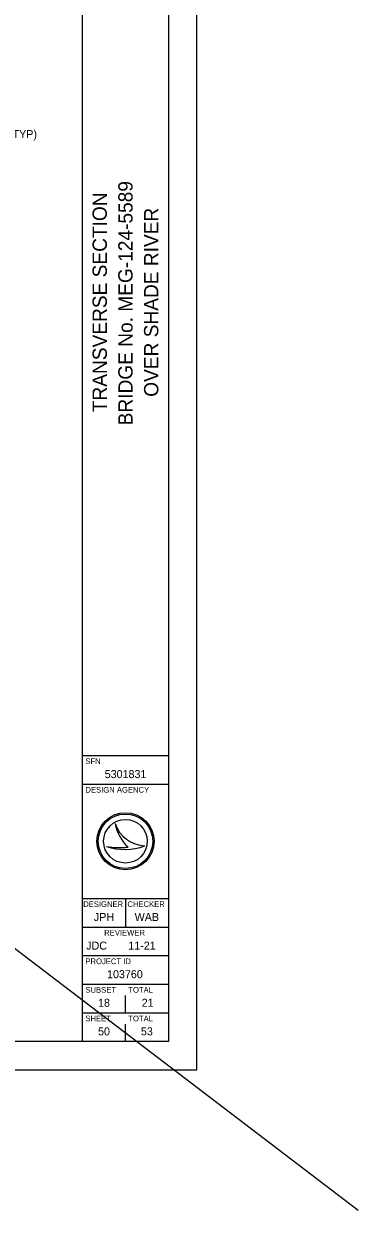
# Model space of a CAD drawing. Extents: x -86 to 68, y -5 to 62.
# Drawn here: x -33.58 to -24.81, y -5.09 to 26.04 of the extents above; entities that cross this region are included whole.
import ezdxf

# ---------------------------------------------------------------- set-up
doc = ezdxf.new("R2010")
doc.units = 0
for name, color, linetype in [('SH_Border', 7, 'Continuous'), ('SH_Cut_Line', 7, 'Continuous'), ('SH_Data', 7, 'Continuous'), ('TX_P_1', 7, 'Continuous')]:
    doc.layers.add(name, color=color, linetype=linetype)

msp = doc.modelspace()

# ---------------------------------------------------------------- linework, layer by layer
at = {"layer": 'SH_Border'}
for p, q in [((-32.038, -0.659), (-32.038, 30.841)), ((-32.038, 6.841), (-29.788, 6.841)), ((-32.038, 6.091), (-29.788, 6.091)), ((-32.038, 3.091), (-29.788, 3.091)), ((-30.913, 3.091), (-30.913, 2.341)), ((-32.038, 2.341), (-29.788, 2.341)), ((-32.038, 1.591), (-29.788, 1.591)), ((-32.038, 0.841), (-29.788, 0.841)), ((-32.038, 0.091), (-29.788, 0.091))]:
    msp.add_line(p, q, dxfattribs=at)
msp.add_lwpolyline([(-77.788, 30.841), (-29.788, 30.841), (-29.788, -0.659), (-77.788, -0.659)], close=True, dxfattribs=at)
at = {"layer": 'SH_Cut_Line'}
msp.add_lwpolyline([(-80.038, -1.409), (-29.038, -1.409), (-29.038, 31.591), (-80.038, 31.591)], close=True, dxfattribs=at)
at = {"layer": 'SH_Data'}
for p, q in [((-31.187, 5.055), (-31.187, 5.055)), ((-31.413, 4.455), (-31.413, 4.455)), ((-30.913, 4.591), (-30.913, 4.591)), ((-30.407, 4.468), (-30.407, 4.468)), ((-30.913, 0.091), (-30.913, 0.541)), ((-30.913, -0.659), (-30.913, -0.209)), ((-31.476, -0.397), (-31.476, -0.397))]:
    msp.add_line(p, q, dxfattribs=at)
for radius in [0.75, 0.715, 0.715, 0.573]:
    msp.add_circle((-30.913, 4.591), radius, dxfattribs=at)
for centre, radius, start, end in [((-30.364, 5.337), 0.87, 198.9257, 198.9319), ((-30.018, 5.296), 1.193, 191.6379, 191.6421), ((-30.364, 5.337), 0.87, 198.9319, 267.1657), ((-30.018, 5.296), 1.193, 191.6421, 226.0947), ((-30.929, 5.896), 1.52, 251.4576, 290.0832), ((-31.066, 6.322), 1.899, 259.4964, 259.4995), ((-30.929, 5.896), 1.52, 251.4527, 251.4576), ((-31.066, 6.322), 1.899, 259.4995, 276.6672)]:
    msp.add_arc(centre, radius, start, end, dxfattribs=at)
at = {"layer": 'TX_P_1'}
msp.add_line((-86.356, 41.867), (-24.807, -5.092), dxfattribs=at)

# ---------------------------------------------------------------- texts
at = {"layer": 'SH_Data'}
for s, p in [('BRIDGE No. MEG-124-5589', (-30.726, 15.504)), ('TRANSVERSE SECTION', (-31.401, 15.848)), ('OVER SHADE RIVER', (-30.051, 16.253))]:
    msp.add_text(s, height=0.375, rotation=90, dxfattribs=at).set_placement(p)
for s, height, p in [('SFN', 0.15, (-31.963, 6.616)), ('5301831', 0.21, (-31.457, 6.248)), ('DESIGN AGENCY', 0.15, (-31.963, 5.866)), ('DESIGNER', 0.15, (-32.022, 2.866)), ('CHECKER', 0.15, (-30.862, 2.866)), ('JPH', 0.21, (-31.741, 2.498)), ('WAB', 0.21, (-30.672, 2.498)), ('REVIEWER', 0.15, (-31.471, 2.116)), ('JDC', 0.21, (-31.943, 1.748)), ('11-21', 0.21, (-30.838, 1.748)), ('PROJECT ID', 0.15, (-31.963, 1.366)), ('103760', 0.21, (-31.396, 0.998)), ('SUBSET', 0.15, (-31.963, 0.616)), ('TOTAL', 0.15, (-30.838, 0.616)), ('18', 0.21, (-31.632, 0.248)), ('21', 0.21, (-30.487, 0.248)), ('SHEET', 0.15, (-31.963, -0.134)), ('TOTAL', 0.15, (-30.838, -0.134)), ('50', 0.21, (-31.632, -0.502)), ('53', 0.21, (-30.507, -0.502))]:
    msp.add_text(s, height=height, dxfattribs=at).set_placement(p)
at = {"layer": 'TX_P_1'}
msp.add_text('TST-1-99 FOR DETAILS (TYP)', height=0.21, dxfattribs=at).set_placement((-37.15, 23.041))

doc.saveas('drawing.dxf')
